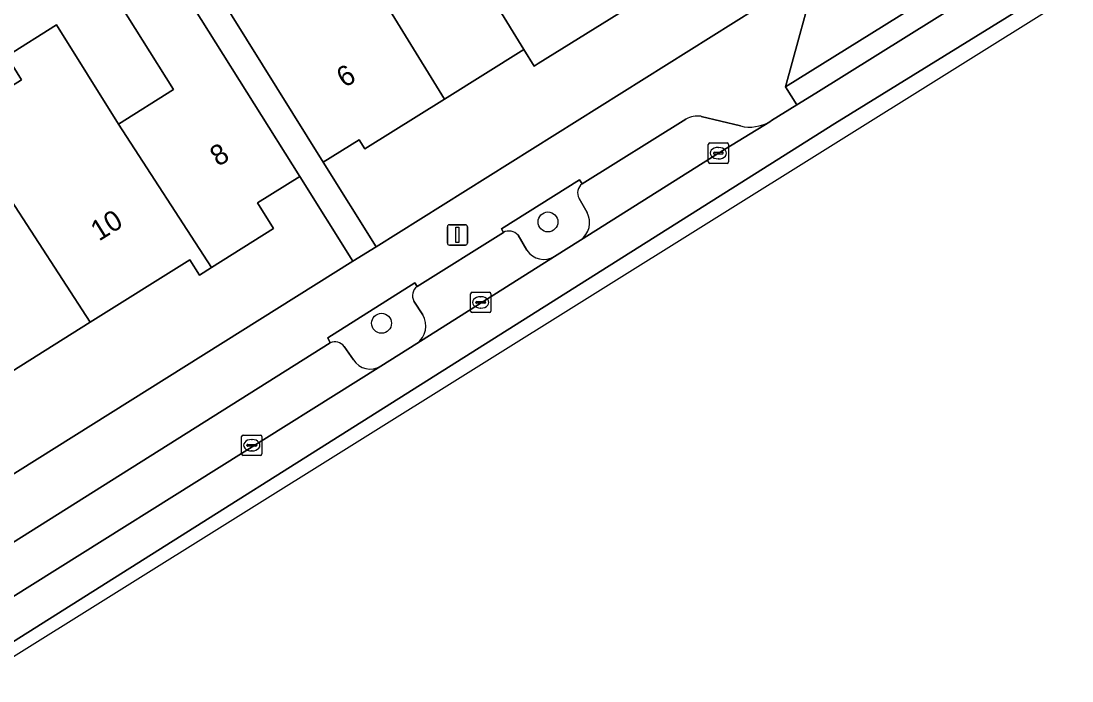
# Model space of a CAD drawing. Extents: x 159352 to 160617, y 385888 to 387323.
# Drawn here: x 159749.7 to 159801.4, y 385938.7 to 385971.1 of the extents above; entities that cross this region are included whole.
import ezdxf

# ---------------------------------------------------------------- set-up
doc = ezdxf.new("R2010")
doc.units = 0
for name, color, linetype in [('IMGEO_Boom', 7, 'Continuous'), ('IMGEO_Erf', 7, 'Continuous'), ('IMGEO_Fietspad_open', 7, 'Continuous'), ('IMGEO_Groenvoorziening', 7, 'Continuous'), ('IMGEO_Kolk', 7, 'Continuous'), ('IMGEO_Lichtmast', 7, 'Continuous'), ('IMGEO_Pand', 7, 'Continuous'), ('IMGEO_Pand_nummerreeks', 7, 'Continuous'), ('IMGEO_Parkeervlak_open', 7, 'Continuous'), ('IMGEO_Rijbaan_regionaal_gesloten', 7, 'Continuous'), ('IMGEO_Voetpad_open', 7, 'Continuous')]:
    doc.layers.add(name, color=color, linetype=linetype)

msp = doc.modelspace()

# ---------------------------------------------------------------- linework, layer by layer
at = {"layer": 'IMGEO_Boom'}
for centre in [(159775.646, 385961.226), (159767.462, 385956.248)]:
    msp.add_circle(centre, 0.489, dxfattribs=at)
at = {"layer": 'IMGEO_Erf'}
msp.add_lwpolyline([(159773.833, 385991.005), (159770.888, 385989.171), (159776.867, 385979.596), (159780.345, 385974.026), (159778.323, 385972.772), (159779.132, 385971.473), (159775.166, 385969.005), (159774.974, 385968.886), (159774.466, 385969.701), (159770.553, 385967.259), (159766.642, 385964.818), (159766.359, 385965.265), (159764.599, 385964.157), (159767.196, 385960.007), (159785.861, 385971.689)], close=True, dxfattribs=at)
for points in [[(159746.736, 385966.308), (159749.764, 385968.215), (159749.038, 385969.373), (159751.478, 385970.903), (159754.533, 385966.031), (159757.235, 385967.726), (159754.181, 385972.598), (159754.683, 385972.913), (159753.567, 385974.69), (159755.595, 385975.963), (159753.911, 385978.646), (159724.622, 385960.426)], [(159736.793, 385940.979), (159766.053, 385959.292), (159763.443, 385963.462), (159761.358, 385962.164), (159762.146, 385960.898), (159759.099, 385958.985), (159758.514, 385958.617), (159758.042, 385959.365), (159753.139, 385956.295), (159747.932, 385953.035)]]:
    msp.add_lwpolyline(points, dxfattribs=at)
at = {"layer": 'IMGEO_Fietspad_open'}
for points in [[(159732.868, 385930.223), (159789.753, 385966.056), (159807.266, 385976.872), (159846.766, 386001.708), (159890.661, 386028.937)], [(159861.026, 386012.714), (159852.337, 386007.274), (159848.877, 386005.124), (159847.204, 386004.039), (159842.911, 386001.399), (159840.679, 386000), (159826.846, 385991.331), (159826.23, 385990.945), (159814.656, 385983.733), (159805.827, 385978.178), (159803.584, 385976.806), (159800.461, 385974.853), (159797.711, 385973.111), (159788.825, 385967.561), (159787.886, 385966.974), (159786.644, 385966.207), (159786.554, 385966.152), (159784.029, 385964.604), (159777.24, 385960.333), (159775.972, 385959.527), (159769.2, 385955.252), (159767.426, 385954.133), (159743.553, 385939.2)]]:
    msp.add_lwpolyline(points, dxfattribs=at)
at = {"layer": 'IMGEO_Groenvoorziening'}
for points in [[(159777.331, 385963.098), (159777.205, 385963.288), (159773.357, 385960.886), (159773.452, 385960.709)], [(159777.568, 385961.697), (159777.177, 385962.376)], [(159774.181, 385960.572), (159774.608, 385959.832)], [(159775.972, 385959.527), (159777.24, 385960.333)], [(159769.21, 385958.05), (159769.097, 385958.228), (159764.823, 385955.524), (159764.94, 385955.286)], [(159769.487, 385956.663), (159769.05, 385957.34)], [(159767.426, 385954.133), (159769.2, 385955.252)], [(159765.62, 385955.105), (159766.075, 385954.449)]]:
    msp.add_lwpolyline(points, dxfattribs=at)
for centre, radius, start, end in [((159777.653, 385962.652), 0.55, 125.822, 210.0969), ((159776.651, 385961.196), 1.045, 304.3106, 28.6471), ((159773.73, 385960.183), 0.595, 40.8209, 117.8923), ((159775.454, 385960.411), 1.025, 214.4182, 300.373), ((159769.537, 385957.603), 0.554, 126.222, 208.3788), ((159768.567, 385956.116), 1.071, 306.2626, 30.743), ((159765.176, 385954.806), 0.535, 33.9781, 116.2115), ((159766.918, 385955.005), 1.009, 213.4215, 300.2488)]:
    msp.add_arc(centre, radius, start, end, dxfattribs=at)
at = {"layer": 'IMGEO_Kolk'}
for p, q in [((159783.602, 385965.105), (159784.454, 385965.105)), ((159783.527, 385964.179), (159783.527, 385965.031)), ((159783.786, 385964.599), (159783.786, 385964.611)), ((159784.224, 385964.562), (159783.826, 385964.562)), ((159783.829, 385964.648), (159784.227, 385964.648)), ((159784.015, 385964.885), (159784.04, 385964.885)), ((159784.27, 385964.611), (159784.27, 385964.599)), ((159784.528, 385965.031), (159784.528, 385964.179)), ((159784.454, 385964.105), (159783.602, 385964.105)), ((159784.038, 385964.325), (159784.013, 385964.325)), ((159771.839, 385956.846), (159771.839, 385957.698)), ((159771.914, 385957.772), (159772.766, 385957.772)), ((159772.141, 385957.315), (159772.539, 385957.315)), ((159772.327, 385957.552), (159772.352, 385957.552)), ((159772.84, 385957.698), (159772.84, 385956.846)), ((159772.766, 385956.772), (159771.914, 385956.772)), ((159772.098, 385957.266), (159772.098, 385957.278)), ((159772.536, 385957.229), (159772.138, 385957.229)), ((159772.35, 385956.992), (159772.325, 385956.992)), ((159772.582, 385957.278), (159772.582, 385957.266)), ((159760.581, 385949.83), (159760.581, 385950.682)), ((159760.656, 385950.756), (159761.508, 385950.756)), ((159761.582, 385950.682), (159761.582, 385949.83)), ((159760.84, 385950.25), (159760.84, 385950.262)), ((159761.278, 385950.213), (159760.88, 385950.213)), ((159760.883, 385950.299), (159761.281, 385950.299)), ((159761.069, 385950.536), (159761.094, 385950.536)), ((159761.324, 385950.262), (159761.324, 385950.25)), ((159761.508, 385949.756), (159760.656, 385949.756)), ((159761.092, 385949.976), (159761.067, 385949.976))]:
    msp.add_line(p, q, dxfattribs=at)
for points in [[(159783.602, 385965.105), (159784.454, 385965.105)], [(159783.527, 385964.179), (159783.527, 385965.031)], [(159784.528, 385965.031), (159784.528, 385964.179)], [(159784.454, 385964.105), (159783.602, 385964.105)], [(159771.839, 385956.846), (159771.839, 385957.698)], [(159771.914, 385957.772), (159772.766, 385957.772)], [(159772.84, 385957.698), (159772.84, 385956.846)], [(159772.766, 385956.772), (159771.914, 385956.772)], [(159760.581, 385949.83), (159760.581, 385950.682)], [(159760.656, 385950.756), (159761.508, 385950.756)], [(159761.582, 385950.682), (159761.582, 385949.83)], [(159761.508, 385949.756), (159760.656, 385949.756)]]:
    msp.add_lwpolyline(points, dxfattribs=at)
for centre, radius, start, end in [((159783.604, 385965.029), 0.0765, 91.552, 178.448), ((159783.604, 385965.029), 0.0765, 91.552, 178.448), ((159784.452, 385965.029), 0.0765, 1.552, 88.448), ((159784.452, 385965.029), 0.0765, 1.552, 88.448), ((159783.826, 385964.608), 0.0403, 85.8775, 175.7526), ((159783.823, 385964.598), 0.0366, 178.938, 274.7102), ((159784.227, 385964.605), 0.043, 264.8664, 352.4533), ((159784.231, 385964.61), 0.0386, 1.7309, 96.639), ((159783.604, 385964.181), 0.0765, 181.552, 268.448), ((159783.604, 385964.181), 0.0765, 181.552, 268.448), ((159784.452, 385964.181), 0.0765, 271.552, 358.448), ((159784.452, 385964.181), 0.0765, 271.552, 358.448), ((159771.916, 385957.696), 0.0765, 91.552, 178.448), ((159771.916, 385957.696), 0.0765, 91.552, 178.448), ((159772.138, 385957.275), 0.0403, 85.8775, 175.7526), ((159772.543, 385957.277), 0.0386, 1.7309, 96.639), ((159772.764, 385957.696), 0.0765, 1.552, 88.448), ((159772.764, 385957.696), 0.0765, 1.552, 88.448), ((159771.916, 385956.848), 0.0765, 181.552, 268.448), ((159771.916, 385956.848), 0.0765, 181.552, 268.448), ((159772.135, 385957.265), 0.0366, 178.938, 274.7102), ((159772.539, 385957.272), 0.043, 264.8664, 352.4533), ((159772.764, 385956.848), 0.0765, 271.552, 358.448), ((159772.764, 385956.848), 0.0765, 271.552, 358.448), ((159760.658, 385950.68), 0.0765, 91.552, 178.448), ((159760.658, 385950.68), 0.0765, 91.552, 178.448), ((159761.506, 385950.68), 0.0765, 1.552, 88.448), ((159761.506, 385950.68), 0.0765, 1.552, 88.448), ((159760.88, 385950.259), 0.0403, 85.8775, 175.7526), ((159760.877, 385950.249), 0.0366, 178.938, 274.7102), ((159761.281, 385950.256), 0.043, 264.8664, 352.4533), ((159761.285, 385950.261), 0.0386, 1.7309, 96.639), ((159760.658, 385949.832), 0.0765, 181.552, 268.448), ((159760.658, 385949.832), 0.0765, 181.552, 268.448), ((159761.506, 385949.832), 0.0765, 271.552, 358.448), ((159761.506, 385949.832), 0.0765, 271.552, 358.448)]:
    msp.add_arc(centre, radius, start, end, dxfattribs=at)
for centre, major_axis, ratio, start_param, end_param in [((159784.014, 385964.605), (-0.387, 0.002), 0.722429, 4.712389, 7.853982), ((159784.039, 385964.605), (-0.39, 0.002), 0.717154, 1.570796, 4.712389), ((159772.326, 385957.272), (-0.387, 0.002), 0.722429, 4.712389, 7.853982), ((159772.351, 385957.272), (-0.39, 0.002), 0.717154, 1.570796, 4.712389), ((159761.068, 385950.256), (-0.387, 0.002), 0.722429, 4.712389, 7.853982), ((159761.093, 385950.256), (-0.39, 0.002), 0.717154, 1.570796, 4.712389)]:
    msp.add_ellipse(centre, major_axis=major_axis, ratio=ratio, start_param=start_param, end_param=end_param, dxfattribs=at)
at = {"layer": 'IMGEO_Lichtmast'}
for p, q in [((159770.698, 385960.188), (159770.698, 385960.988)), ((159770.698, 385960.988), (159770.698, 385960.188)), ((159770.798, 385961.088), (159771.588, 385961.088)), ((159771.588, 385961.088), (159770.798, 385961.088)), ((159771.688, 385960.988), (159771.688, 385960.188)), ((159771.688, 385960.188), (159771.688, 385960.988)), ((159771.588, 385960.088), (159770.798, 385960.088)), ((159770.798, 385960.088), (159771.588, 385960.088))]:
    msp.add_line(p, q, dxfattribs=at)
msp.add_lwpolyline([(159771.118, 385960.963), (159771.268, 385960.963), (159771.268, 385960.213), (159771.118, 385960.213), (159771.118, 385960.963)], dxfattribs=at)
for centre, start, end in [((159770.798, 385960.988), 90, 180), ((159770.798, 385960.988), 90, 180), ((159771.588, 385960.988), 0, 90), ((159771.588, 385960.988), 360, 90), ((159770.798, 385960.188), 180, 270), ((159770.798, 385960.188), 180, 270), ((159771.588, 385960.188), 270, 0), ((159771.588, 385960.188), 270, 0)]:
    msp.add_arc(centre, 0.1, start, end, dxfattribs=at)
at = {"layer": 'IMGEO_Pand'}
for points in [[(159774.974, 385968.886), (159775.166, 385969.005), (159779.132, 385971.473), (159778.323, 385972.772), (159780.345, 385974.026), (159776.867, 385979.596), (159770.888, 385989.171), (159767.632, 385987.153), (159769.345, 385984.391), (159767.365, 385983.163), (159771.385, 385976.678), (159770.515, 385976.138), (159774.466, 385969.701)], [(159774.466, 385969.701), (159770.515, 385976.138), (159769.142, 385975.287), (159766.112, 385980.174), (159763.562, 385978.593), (159766.592, 385973.706), (159770.553, 385967.259)], [(159763.371, 385971.709), (159760.341, 385976.596), (159757.842, 385975.011), (159764.599, 385964.157), (159766.359, 385965.265), (159766.642, 385964.818), (159770.553, 385967.259), (159766.592, 385973.706)], [(159756.712, 385974.184), (159755.595, 385975.963), (159753.567, 385974.69), (159754.683, 385972.913), (159754.181, 385972.598), (159757.235, 385967.726), (159754.533, 385966.031), (159759.099, 385958.985), (159762.146, 385960.898), (159761.358, 385962.164), (159763.443, 385963.462)], [(159754.533, 385966.031), (159751.478, 385970.903), (159749.038, 385969.373), (159749.764, 385968.215), (159746.736, 385966.308), (159749.055, 385962.597), (159753.139, 385956.295), (159758.042, 385959.365), (159758.514, 385958.617), (159759.099, 385958.985)], [(159747.932, 385953.035), (159753.139, 385956.295), (159749.055, 385962.597), (159746.017, 385960.693), (159742.963, 385965.565), (159740.722, 385964.16)]]:
    msp.add_lwpolyline(points, close=True, dxfattribs=at)
at = {"layer": 'IMGEO_Parkeervlak_open'}
for points in [[(159777.24, 385960.333), (159784.029, 385964.604), (159786.554, 385966.152)], [(159782.431, 385966.279), (159777.331, 385963.098)], [(159785.108, 385965.94), (159783.179, 385966.414)], [(159777.177, 385962.376), (159777.568, 385961.697)], [(159773.452, 385960.709), (159769.21, 385958.05)], [(159774.608, 385959.832), (159774.181, 385960.572)], [(159769.2, 385955.252), (159775.972, 385959.527)], [(159769.05, 385957.34), (159769.487, 385956.663)], [(159764.94, 385955.286), (159745.314, 385942.959)], [(159766.075, 385954.449), (159765.62, 385955.105)], [(159743.553, 385939.2), (159767.426, 385954.133)]]:
    msp.add_lwpolyline(points, dxfattribs=at)
for centre, radius, start, end in [((159782.995, 385965.296), 1.134, 80.6421, 119.8193), ((159785.563, 385967.871), 1.984, 256.7336, 299.948), ((159777.653, 385962.652), 0.55, 125.822, 210.0969), ((159776.651, 385961.196), 1.045, 304.3106, 28.6471), ((159773.73, 385960.183), 0.595, 40.8209, 117.8923), ((159775.454, 385960.411), 1.025, 214.4182, 300.373), ((159769.537, 385957.603), 0.554, 126.222, 208.3788), ((159768.567, 385956.116), 1.071, 306.2626, 30.743), ((159765.176, 385954.806), 0.535, 33.9781, 116.2115), ((159766.918, 385955.005), 1.009, 213.4215, 300.2488)]:
    msp.add_arc(centre, radius, start, end, dxfattribs=at)
at = {"layer": 'IMGEO_Rijbaan_regionaal_gesloten'}
for points in [[(159680.589, 385901.515), (159678.374, 385900.403), (159677.09, 385899.832), (159676.054, 385899.376), (159674.34, 385898.621), (159673.604, 385898.41), (159672.377, 385898.152), (159671.133, 385898.005), (159669.88, 385897.969), (159668.841, 385898.033), (159672.265, 385892.74), (159701.42, 385910.447), (159730.336, 385928.01), (160003.316, 386098.383), (160029.667, 386114.83), (160338.731, 386306.963), (160519.651, 386421.283), (160554.007, 386449.857), (160584.37, 386476.501)], [(160004.347, 386101.103), (160002.357, 386099.871), (159999.724, 386098.31), (159991.642, 386093.359), (159989.333, 386091.543), (159985.375, 386088.326), (159946.201, 386063.73), (159920.298, 386047.584), (159890.661, 386028.937), (159846.766, 386001.708), (159807.266, 385976.872), (159789.753, 385966.056), (159732.868, 385930.223), (159726.624, 385926.948)]]:
    msp.add_lwpolyline(points, dxfattribs=at)
at = {"layer": 'IMGEO_Voetpad_open'}
for points in [[(159757.842, 385975.011), (159755.113, 385979.394), (159753.911, 385978.646), (159755.595, 385975.963), (159756.712, 385974.184), (159763.443, 385963.462), (159766.053, 385959.292), (159767.196, 385960.007), (159764.599, 385964.157)], [(159797.16, 385973.993), (159792.94, 385976.214), (159788.912, 385973.68), (159787.335, 385967.856)], [(159787.886, 385966.974), (159788.825, 385967.561), (159797.711, 385973.111), (159797.16, 385973.993), (159787.335, 385967.856)]]:
    msp.add_lwpolyline(points, close=True, dxfattribs=at)
for points in [[(159786.554, 385966.152), (159786.644, 385966.207), (159787.886, 385966.974), (159787.335, 385967.856), (159788.912, 385973.68), (159785.861, 385971.689), (159767.196, 385960.007), (159766.053, 385959.292), (159736.793, 385940.979), (159733.652, 385939.014), (159740.1, 385938.269), (159740.644, 385937.383), (159743.553, 385939.2)], [(159764.94, 385955.286), (159764.823, 385955.524), (159769.097, 385958.228), (159769.21, 385958.05), (159773.452, 385960.709), (159773.357, 385960.886), (159777.205, 385963.288), (159777.331, 385963.098), (159782.431, 385966.279)], [(159783.179, 385966.414), (159785.108, 385965.94)], [(159745.314, 385942.959), (159764.94, 385955.286)]]:
    msp.add_lwpolyline(points, dxfattribs=at)
for centre, radius, start, end in [((159782.995, 385965.296), 1.134, 80.6421, 119.8193), ((159785.563, 385967.871), 1.984, 256.7336, 299.948)]:
    msp.add_arc(centre, radius, start, end, dxfattribs=at)

# ---------------------------------------------------------------- texts
at = {"layer": 'IMGEO_Pand_nummerreeks'}
for s, rotation, p in [('6', 32.0782, (159765.652, 385967.792)), ('8', 32.0112, (159759.428, 385963.921)), ('10', 32.0112, (159753.563, 385960.255))]:
    msp.add_text(s, height=1, rotation=rotation, dxfattribs=at).set_placement(p)

doc.saveas('drawing.dxf')
